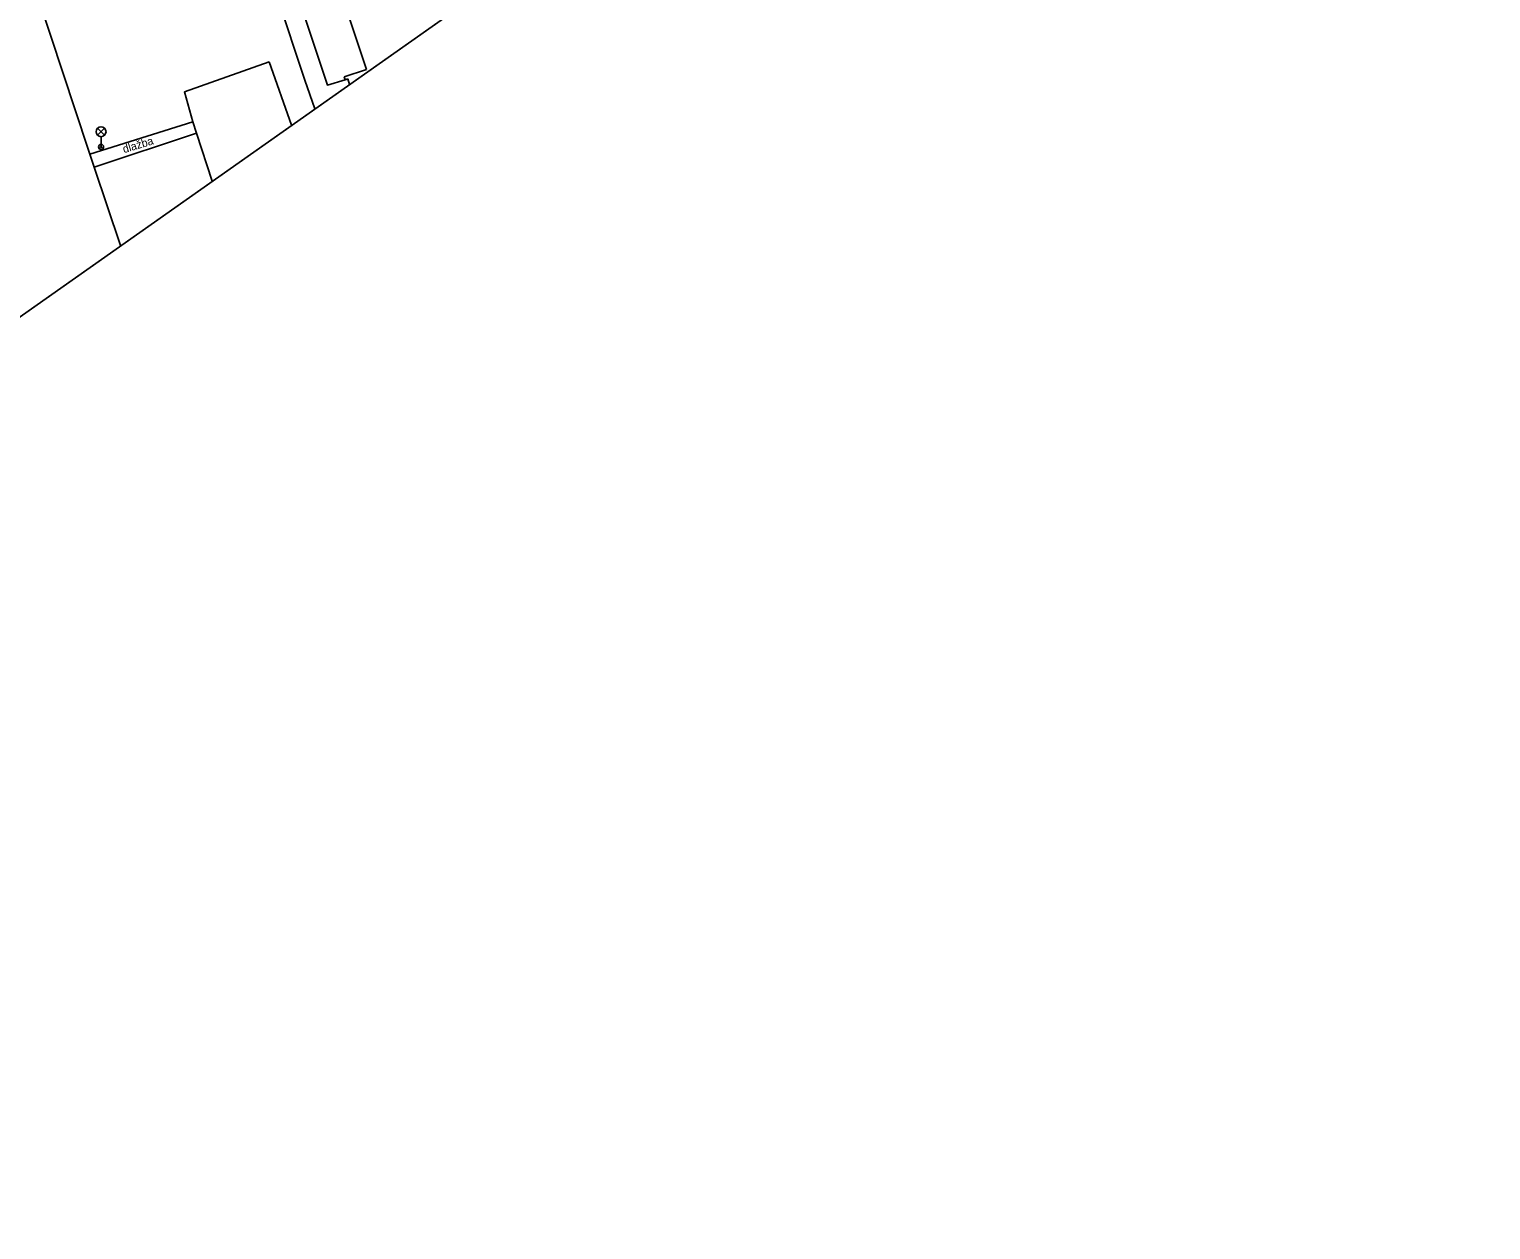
# Model space of a CAD drawing. Extents: x -492431 to -49218, y -1127123 to -112687.
# Drawn here: x -492243 to -492133, y -1127122.9 to -1127032.6 of the extents above; entities that cross this region are included whole.
import ezdxf

# ---------------------------------------------------------------- set-up
doc = ezdxf.new("R2010")
doc.units = 0
for name, color, linetype in [('Vrstva 1', 7, 'Continuous'), ('Vrstva 10', 7, 'Continuous'), ('Vrstva 11', 7, 'Continuous'), ('Vrstva 33', 7, 'Continuous'), ('Vrstva 40', 7, 'Continuous'), ('Vrstva 5', 7, 'Continuous'), ('Vrstva 60', 7, 'Continuous')]:
    doc.layers.add(name, color=color, linetype=linetype)

msp = doc.modelspace()

# ---------------------------------------------------------------- linework, layer by layer
at = {"layer": 'Vrstva 1'}
msp.add_lwpolyline([(-492341.24, -1127122.91), (-492133.03, -1126976.26), (-492272.7, -1126862.46), (-492313.78, -1126867.2)], dxfattribs=at)
at = {"layer": 'Vrstva 10'}
for p, q in [((-492231.67, -1127008.24), (-492222.27, -1127036.44)), ((-492242.51, -1127029.7), (-492238.59, -1127041.62)), ((-492223.27, -1127039.82), (-492224.95, -1127035.05)), ((-492222.27, -1127036.44), (-492221.53, -1127038.6)), ((-492230.7, -1127039.56), (-492238.46, -1127042)), ((-492238.13, -1127042.98), (-492230.42, -1127040.41))]:
    msp.add_line(p, q, dxfattribs=at)
for points in [[(-492219.23, -1127036.4), (-492220.57, -1127036.8), (-492225.52, -1127021.94), (-492224.18, -1127021.47)], [(-492224.95, -1127035.05), (-492231.34, -1127037.31), (-492230.7, -1127039.56)], [(-492230.42, -1127040.41), (-492229.25, -1127044.03)], [(-492236.14, -1127048.88), (-492238.13, -1127042.98), (-492238.46, -1127042), (-492238.59, -1127041.62)]]:
    msp.add_lwpolyline(points, dxfattribs=at)
at = {"layer": 'Vrstva 11'}
msp.add_lwpolyline([(-492230.7, -1127039.56), (-492230.42, -1127040.41)], dxfattribs=at)
at = {"layer": 'Vrstva 33'}
for p, q in [((-492237.88, -1127040.05), (-492237.35, -1127040.57)), ((-492237.88, -1127040.57), (-492237.35, -1127040.05)), ((-492237.61, -1127041.46), (-492237.61, -1127040.69))]:
    msp.add_line(p, q, dxfattribs=at)
for centre, radius in [((-492237.61, -1127040.31), 0.375), ((-492237.61, -1127041.46), 0.19), ((-492237.61, -1127041.46), 0.05)]:
    msp.add_circle(centre, radius, dxfattribs=at)
at = {"layer": 'Vrstva 5'}
for p, q in [((-492217.64, -1127035.64), (-492219.31, -1127036.19)), ((-492219.23, -1127036.4), (-492219.31, -1127036.19)), ((-492219.04, -1127036.34), (-492219.23, -1127036.4)), ((-492218.91, -1127036.75), (-492219.04, -1127036.34))]:
    msp.add_line(p, q, dxfattribs=at)
msp.add_lwpolyline([(-492217.64, -1127035.64), (-492220.44, -1127027.15)], dxfattribs=at)
at = {"layer": 'Vrstva 60'}
msp.add_lwpolyline([(-492431.03, -1127000), (-492431.03, -1127013.12), (-492341.24, -1127122.91), (-492166.73, -1127000)], dxfattribs=at)

# ---------------------------------------------------------------- texts
at = {"layer": 'Vrstva 40'}
msp.add_text('dlažba', height=0.6, rotation=16.8865, dxfattribs=at).set_placement((-492235.88, -1127041.93))

doc.saveas('drawing.dxf')
